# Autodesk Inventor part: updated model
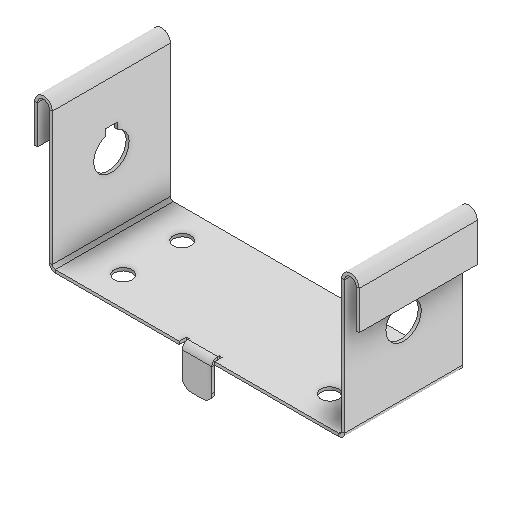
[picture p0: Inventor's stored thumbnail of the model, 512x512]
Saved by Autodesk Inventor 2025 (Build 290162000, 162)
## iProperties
Created: 2021-06
Part Number: updated model
Material: Generic
Document SubType Name: Sheet Metal
Designer: ASUS Laptop
Density: 1 g/cm^3
Flat Pattern Width: 5.12619 cm
Flat Pattern Length: 23.1855 cm
Flat Pattern Area: 118.853 cm^2
Sheet Metal Rule: Default_mm
Sheet Metal Width: 51.262 mm
Sheet Metal Length: 231.855 mm
Sheet Metal Area: 11885.332 mm^2
Appearance: Default
Author: ASUS Laptop
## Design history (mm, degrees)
node "Face1"
sketch "Sketch3"
  geometry: L1 (0, 0)-(0, 40) reference; L2 (100, 0)-(0, 0) reference; 1 further point
  dimensions: "d3" = 15 distance from line of L1 point (15, 10); "d4" = 10 distance from line of L2 point (15, 10)
hole "Hole1" sketch "Sketch3" diameter "d5" = 6; stored, may be unused: countersink angle "d9" = 90 deg, drill point angle "d11" = 118 deg; dims "d6" = 6, "d7" = 6, "d8" = 2, "d10" = 1 (= Thickness)
pattern_linear "Rectangular Pattern1" dims "d17" = 70
node "Flange1"
feature "Hem1" dims "d2" = 1 (= Thickness), "d28" = 1 (= BendReliefWidth), "d29" = 0.5 (= BendReliefDepth), "d30" = 2 (= MinimumRemnant), "d31" = 1 (= TransitionRadius), "d32" = 16, "d33" = 4, "d34" = 2 (= 0.5 x d33), "SeamGap" = 0.01
feature "Hem2" dims "d2" = 1 (= Thickness), "d35" = 1 (= BendReliefWidth), "d36" = 0.5 (= BendReliefDepth), "d37" = 2 (= MinimumRemnant), "d38" = 1 (= TransitionRadius), "d39" = 16, "d40" = 4, "d41" = 2 (= 0.5 x d40), "SeamGap" = 0.01
feature "iFeature15:1"
feature "iFeature15:2"
node "Flange2"
feature "Corner Round1" dims "d69" = 3
body "Solid1"
sketch "Sketch2"
  geometry: L1 (0, 0)-(-100, 0); L2 (-100, 0)-(-100, -40); L3 (-100, -40)-(0, -40); L4 (0, -40)-(0, 0)
  constraints: 8 end point, 2 parallel, 1 horizontal, 1 perpendicular
  dimensions: "d0" = 40 distance of L3.end L1.start; "d1" = 100 distance of L2.end L3.end
face "Plate1" dims "d2" = 1 (= Thickness)
sketch "Sketch4"
  geometry: L1 through (0, -20) direction (-5.44e-32, 1); L2 through (-25, 0) direction (-1, -9.38e-32); L3 (-50, 0)-(-50, -40); L4 (-50, -40)-(0, -40)
  constraints: 6 end point, 1 horizontal, 1 perpendicular, 1 vertical
face "Plate2" dims "d2" = 1 (= Thickness), "d18" = 1 (= BendReliefWidth), "d19" = 0.5 (= BendReliefDepth), "d20" = 2 (= MinimumRemnant), "d21" = 1 (= TransitionRadius), "d22" = 50, "d23" = 90 deg, "d24" = 1 (= BendRadius), "d25" = 4 (= CornerReliefSize), "d26" = 1 (= GapSize), "d27" = 1 (= JacobiRadiusSize), "SeamGap" = 0.01
bend "Bend1" dims "d2" = 1 (= Thickness), "d18" = 1 (= BendReliefWidth), "d19" = 0.5 (= BendReliefDepth), "d20" = 2 (= MinimumRemnant), "d21" = 1 (= TransitionRadius), "d22" = 50, "d23" = 90 deg, "d24" = 1 (= BendRadius), "SeamGap" = 0.01
feature "Corner1" dims "d22" = 50, "d23" = 90 deg, "d25" = 4 (= CornerReliefSize), "d26" = 1 (= GapSize), "d27" = 1 (= JacobiRadiusSize)
sketch "Sketch7"
  geometry: L1 (0, 0)-(40, 0) reference; L2 (40, 0)-(40, -48) reference; 2 further points
  dimensions: "d42" = 25 distance from line of point (20, -25) L1; "d43" = 20 distance from line of L2 point (20, -25)
sketch "Sketch8"
  geometry: L1 (40, 0)-(0, 0) reference; L2 (40, -48)-(40, 0) reference; 2 further points
  dimensions: "d50" = 25 distance from line of point (20, -25) L1; "d51" = 20 distance from line of point (20, -25) L2
sketch "Sketch9"
  geometry: L1 (-53, 0)-(-43, 0); L2 (-43, 0)-(-43, 13); L3 (-43, 13)-(-53, 13); L4 (-53, 13)-(-53, 0)
  constraints: 8 end point
face "Plate3" dims "d2" = 1 (= Thickness), "d58" = 1 (= BendReliefWidth), "d59" = 0.5 (= BendReliefDepth), "d60" = 2 (= MinimumRemnant), "d61" = 1 (= TransitionRadius), "d62" = 10, "d63" = 13, "d64" = 90 deg, "d65" = 1 (= BendRadius), "d66" = 4 (= CornerReliefSize), "d67" = 1 (= GapSize), "d68" = 1 (= JacobiRadiusSize), "SeamGap" = 0.01
bend "Bend2" dims "d2" = 1 (= Thickness), "d58" = 1 (= BendReliefWidth), "d59" = 0.5 (= BendReliefDepth), "d60" = 2 (= MinimumRemnant), "d61" = 1 (= TransitionRadius), "d63" = 13, "d64" = 90 deg, "d65" = 1 (= BendRadius), "SeamGap" = 0.01
feature "Corner2" dims "d63" = 13, "d64" = 90 deg, "d66" = 4 (= CornerReliefSize), "d67" = 1 (= GapSize), "d68" = 1 (= JacobiRadiusSize)
sketch "Sketch5"
  geometry: L1 (1, 0)-(0, 0); L2 (-4, 0)-(-4, -13); L3 (-4, -13)-(-5, -13); L4 (-5, -13)-(-5, 0); A1 r 2 centre (-2, 0) between (0, 0) and (-4, 0); A2 r 3 centre (-2, 0) between (1, 0) and (-5, 0)
  constraints: 8 end point, 4 point on circle
sketch "Sketch6"
  geometry: L1 (1, 0)-(0, 0); L2 (-4, 0)-(-4, -13); L3 (-4, -13)-(-5, -13); L4 (-5, -13)-(-5, 0); A1 r 2 centre (-2, 0) between (0, 0) and (-4, 0); A2 r 3 centre (-2, 0) between (1, 0) and (-5, 0)
  constraints: 8 end point, 4 point on circle
feature "Definition1"
other parameters: "Thickness" = 1 (derived), "BendRadius" = 1 (= Thickness), "BendReliefWidth" = 1 (= Thickness), "BendReliefDepth" = 0.5 (= 0.5 x Thickness), "CornerReliefSize" = 4 (= 4 x Thickness), "MinimumRemnant" = 2 (= 2 x Thickness), "TransitionRadius" = 1 (= BendRadius), "JacobiRadiusSize" = 1 (= BendRadius), "GapSize" = 1 (= Thickness), "d49" = 0, "d57" = 0, "BendRadius" = 1, "BendReliefDepth" = 0.5, "BendReliefWidth" = 1, "CornerReliefSize" = 4, "GapSize" = 1, "JacobiRadiusSize" = 1, "MinimumRemnant" = 2, "Thickness" = 1, "TransitionRadius" = 1
